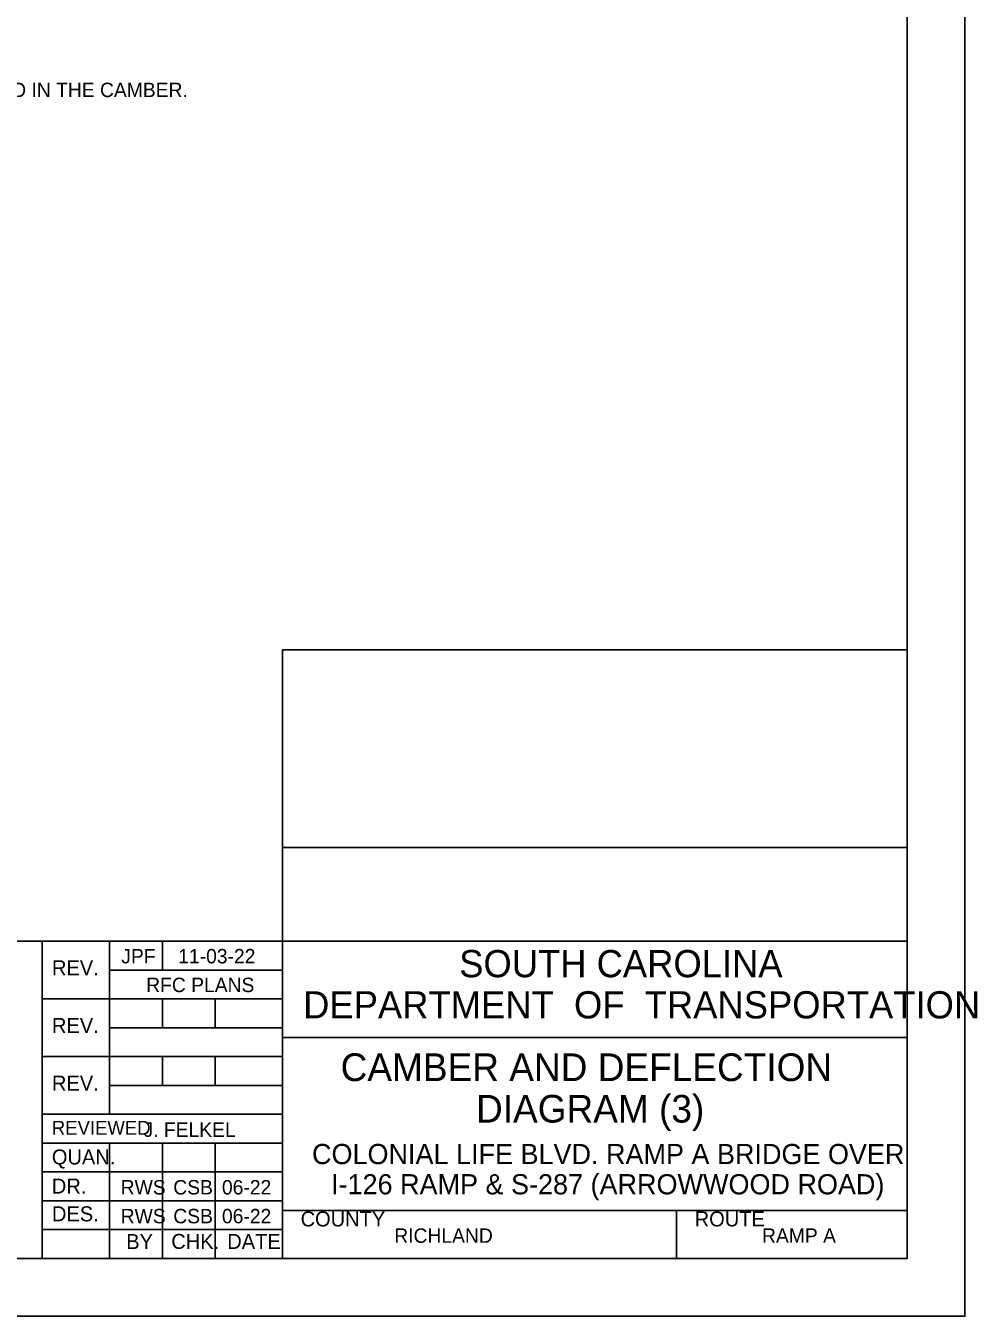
# Model space of a CAD drawing. Extents: x -125.5 to -89.4, y -5.1 to 16.9.
# Drawn here: x -97.68 to -89.43, y -5.07 to 6.12 of the extents above; entities that cross this region are included whole.
import ezdxf

# ---------------------------------------------------------------- set-up
doc = ezdxf.new("R2010")
doc.units = 0
for name, color, linetype in [('BR_AUTO DIMENSION', 7, 'Continuous'), ('BR_BORDER LINES', 7, 'Continuous'), ('BR_TABLE LINES', 7, 'Continuous'), ('BR_TEXT', 7, 'Continuous'), ('Level 31', 7, 'Continuous')]:
    doc.layers.add(name, color=color, linetype=linetype)

msp = doc.modelspace()

# ---------------------------------------------------------------- linework, layer by layer
at = {"layer": 'BR_BORDER LINES'}
for p, q in [((-90.033, -4.566), (-90.033, 16.434)), ((-95.45, -4.566), (-95.45, 0.71)), ((-95.45, 0.71), (-90.033, 0.71)), ((-95.45, -1.004), (-90.033, -1.004)), ((-102.899, -1.816), (-97.534, -1.816)), ((-97.534, -4.566), (-97.534, -1.816)), ((-97.534, -1.816), (-90.033, -1.816)), ((-96.95, -1.816), (-96.95, -3.316)), ((-96.492, -2.066), (-96.492, -1.816)), ((-96.95, -2.066), (-95.45, -2.066)), ((-97.534, -2.316), (-95.45, -2.316)), ((-96.492, -2.566), (-96.492, -2.316)), ((-96.034, -2.566), (-96.034, -2.316)), ((-96.95, -2.566), (-95.45, -2.566)), ((-95.45, -2.649), (-95.45, -2.649)), ((-95.45, -2.649), (-90.033, -2.649)), ((-97.534, -2.816), (-95.45, -2.816)), ((-96.492, -3.066), (-96.492, -2.816)), ((-96.034, -3.066), (-96.034, -2.816)), ((-96.95, -3.066), (-95.45, -3.066)), ((-97.534, -3.316), (-95.45, -3.316)), ((-97.534, -3.566), (-95.45, -3.566)), ((-96.95, -3.566), (-96.95, -4.566)), ((-96.492, -3.566), (-96.492, -4.566)), ((-96.034, -3.566), (-96.034, -4.566)), ((-97.534, -3.816), (-95.45, -3.816)), ((-97.534, -4.066), (-95.45, -4.066)), ((-95.45, -4.149), (-90.033, -4.149)), ((-95.353, -4.149), (-90.033, -4.149)), ((-92.033, -4.566), (-92.033, -4.149)), ((-97.534, -4.316), (-95.45, -4.316)), ((-123.699, -4.566), (-90.033, -4.566))]:
    msp.add_line(p, q, dxfattribs=at)
at = {"layer": 'BR_TABLE LINES'}
msp.add_lwpolyline([(-123.699, 16.434), (-90.033, 16.434), (-90.033, -4.566), (-123.699, -4.566)], close=True, dxfattribs=at)
at = {"layer": 'Level 31'}
msp.add_line((-92.742, -3.09), (-92.742, -3.09), dxfattribs=at)
msp.add_lwpolyline([(-125.533, 16.934), (-125.533, -5.066), (-89.533, -5.066), (-89.533, 16.934)], dxfattribs=at)

# ---------------------------------------------------------------- texts
at = {"layer": 'BR_AUTO DIMENSION'}
msp.add_text('SUPERELEVATION ORDINATES ARE INCLUDED IN THE CAMBER.', height=0.125, dxfattribs=at).set_placement((-101.5, 5.501))
at = {"layer": 'BR_TEXT'}
for s, height, p in [('JPF', 0.125, (-96.848, -2.008)), ('11-03-22', 0.125, (-96.354, -2.008)), ('SOUTH CAROLINA', 0.23587, (-93.918, -2.128)), ('REV.', 0.13, (-97.449, -2.111)), ('RFC PLANS', 0.125, (-96.632, -2.257)), ('DEPARTMENT  OF  TRANSPORTATION', 0.23587, (-95.271, -2.485)), ('REV.', 0.13, (-97.449, -2.611)), ('CAMBER AND DEFLECTION', 0.24, (-94.946, -3.028)), ('REV.', 0.13, (-97.449, -3.111)), ('DIAGRAM (3)', 0.24, (-93.772, -3.388)), ('REVIEWED', 0.12, (-97.45, -3.493)), ('J. FELKEL', 0.125, (-96.655, -3.512)), ('COLONIAL LIFE BLVD. RAMP A BRIDGE OVER', 0.175, (-95.194, -3.748)), ('QUAN.', 0.13, (-97.45, -3.751)), ('DR.', 0.13, (-97.45, -4.003)), ('RWS', 0.125, (-96.853, -4.011)), ('CSB', 0.125, (-96.397, -4.011)), ('06-22', 0.125, (-95.975, -4.011)), ('I-126 RAMP & S-287 (ARROWWOOD ROAD)', 0.175, (-95.029, -4.01)), ('DES.', 0.13, (-97.449, -4.244)), ('RWS', 0.125, (-96.853, -4.261)), ('CSB', 0.125, (-96.397, -4.261)), ('06-22', 0.125, (-95.975, -4.261)), ('COUNTY', 0.13, (-95.293, -4.288)), ('ROUTE', 0.13, (-91.876, -4.288)), ('BY', 0.13, (-96.805, -4.484)), ('CHK.', 0.13, (-96.414, -4.483)), ('DATE', 0.13, (-95.929, -4.483)), ('RICHLAND', 0.125, (-94.481, -4.43)), ('RAMP A', 0.125, (-91.292, -4.43))]:
    msp.add_text(s, height=height, dxfattribs=at).set_placement(p)

doc.saveas('drawing.dxf')
